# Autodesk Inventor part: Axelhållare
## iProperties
Created: 2001-12
Part Number: Axelhållare
Material: SS2172
Document SubType Name: Modeling
Designer: Tobben
Control State: 0
Master: False
Checked Out: False
Shininess: 64.0
Length Units: 11269
Angle Units: 11279
Time Units: 11290
Mass Units: 11283
Length Display Precision: 3
Angle Display Precision: 2
Density: 0.0
Volumn: 0.0
Area: 0.0
PropertySet Name: Model Information
Author: Tobben
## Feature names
1. Extrusion1
2. Chamfer1
3. Hole1
